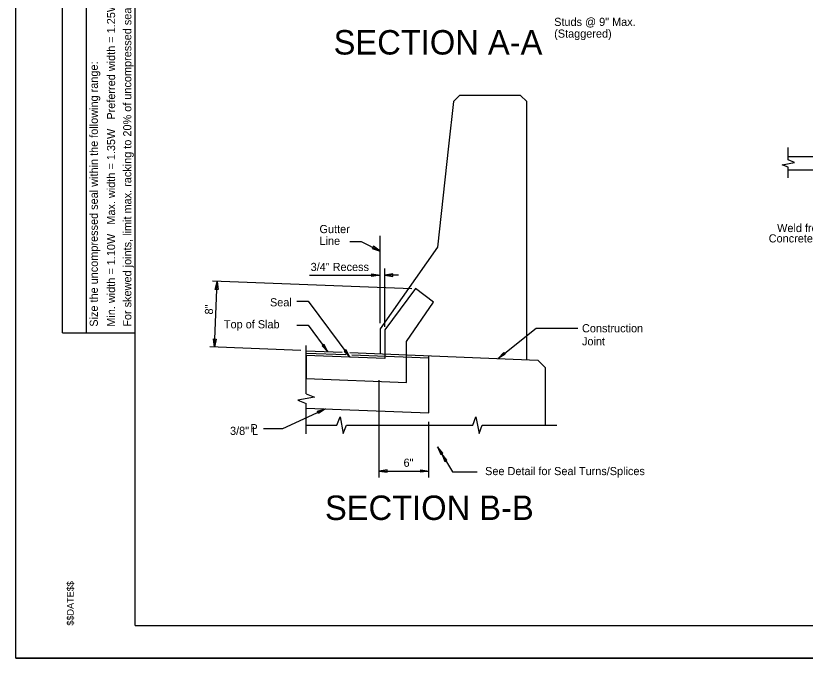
# Model space of a CAD drawing. Extents: x 3.7 to 39.9, y -2.3 to 19.7.
# Drawn here: x 3.74 to 15.85, y -2.32 to 7.54 of the extents above; entities that cross this region are included whole.
import ezdxf

# ---------------------------------------------------------------- set-up
doc = ezdxf.new("R2010")
doc.units = 0
for name, color, linetype in [('BR_AUTO DIMENSION', 7, 'Continuous'), ('BR_BORDER LINES', 7, 'Continuous'), ('BR_CENTER LINES', 7, 'Continuous'), ('BR_CONCRETE', 7, 'Continuous'), ('BR_REBAR', 7, 'Continuous'), ('BR_STRUCTURAL STEEL', 7, 'Continuous'), ('BR_TABLE LINES', 7, 'Continuous'), ('BR_TEXT', 7, 'Continuous'), ('RD_SHT_IplotShp', 7, 'Continuous')]:
    doc.layers.add(name, color=color, linetype=linetype)

msp = doc.modelspace()

# ---------------------------------------------------------------- linework, layer by layer
at = {"layer": 'BR_AUTO DIMENSION'}
for p, q in [((9.328, 2.823), (9.328, 4.162)), ((8.865, 4.077), (9.04, 4.077)), ((9.04, 4.077), (9.328, 3.929)), ((9.401, 2.766), (9.401, 3.66)), ((8.243, 3.56), (9.328, 3.56)), ((9.611, 3.56), (9.401, 3.56)), ((9.814, 3.351), (6.755, 3.467)), ((6.786, 2.455), (6.825, 3.464)), ((8.051, 3.163), (8.225, 3.163)), ((8.225, 3.163), (8.865, 2.302)), ((8.05, 2.795), (8.224, 2.795)), ((8.224, 2.795), (8.528, 2.386)), ((11.141, 2.283), (11.723, 2.749)), ((11.723, 2.749), (12.361, 2.749)), ((8.111, 2.405), (6.717, 2.458)), ((9.314, 0.454), (9.314, 1.947)), ((7.835, 1.205), (8.488, 1.508)), ((10.076, 0.454), (10.076, 1.312)), ((7.54, 1.205), (7.835, 1.205)), ((10.21, 0.926), (10.44, 0.544)), ((9.314, 0.555), (10.076, 0.555)), ((10.44, 0.544), (10.819, 0.544))]:
    msp.add_line(p, q, dxfattribs=at)
for points in [[(9.208, 3.97), (9.328, 3.929), (9.225, 4.003)], [(9.203, 3.579), (9.328, 3.56), (9.203, 3.541)], [(9.526, 3.579), (9.401, 3.56), (9.526, 3.541)], [(6.799, 3.34), (6.825, 3.464), (6.841, 3.339)], [(6.812, 2.579), (6.786, 2.455), (6.77, 2.581)], [(8.438, 2.476), (8.528, 2.386), (8.468, 2.498)], [(8.776, 2.391), (8.865, 2.302), (8.806, 2.413)], [(11.25, 2.346), (11.141, 2.283), (11.227, 2.375)], [(8.367, 1.473), (8.488, 1.508), (8.383, 1.439)], [(10.291, 0.829), (10.21, 0.926), (10.258, 0.809)], [(10.355, 0.722), (10.275, 0.819), (10.323, 0.702)], [(9.439, 0.574), (9.314, 0.555), (9.439, 0.536)], [(9.951, 0.574), (10.076, 0.555), (9.951, 0.536)]]:
    msp.add_lwpolyline(points, close=True, dxfattribs=at)
at = {"layer": 'BR_BORDER LINES'}
for p, q in [((5.57, -1.817), (5.57, 19.183)), ((5.57, -1.817), (39.236, -1.817)), ((3.736, -2.316), (39.736, -2.316))]:
    msp.add_line(p, q, dxfattribs=at)
at = {"layer": 'BR_CENTER LINES'}
for points in [[(8.192, 1.737), (8.321, 1.689), (8.064, 1.641), (8.192, 1.592)], [(8.666, 1.259), (8.715, 1.388), (8.763, 1.131), (8.811, 1.259)], [(10.752, 1.259), (10.8, 1.388), (10.848, 1.131), (10.896, 1.259)]]:
    msp.add_lwpolyline(points, dxfattribs=at)
at = {"layer": 'BR_CONCRETE'}
for p, q in [((10.547, 6.316), (10.453, 6.222)), ((11.484, 6.316), (10.547, 6.316)), ((11.578, 6.222), (11.484, 6.316)), ((10.453, 6.222), (10.378, 5.537)), ((11.578, 2.269), (11.578, 6.222)), ((10.378, 5.537), (10.209, 3.992)), ((10.209, 3.992), (9.328, 2.734)), ((9.328, 2.734), (9.328, 2.359)), ((8.192, 2.401), (8.748, 2.378)), ((8.863, 2.374), (11.748, 2.258)), ((9.457, 2.353), (9.457, 2.35)), ((10.076, 1.448), (10.076, 2.325)), ((11.866, 2.14), (11.748, 2.258)), ((11.866, 1.259), (11.866, 2.14))]:
    msp.add_line(p, q, dxfattribs=at)
at = {"layer": 'BR_REBAR'}
msp.add_line((8.192, 2.364), (8.804, 2.341), dxfattribs=at)
at = {"layer": 'BR_STRUCTURAL STEEL'}
for p, q in [((15.594, 5.383), (20.419, 5.383)), ((15.594, 5.177), (18.113, 5.177)), ((8.892, 2.338), (10.076, 2.293)), ((8.192, 1.519), (10.076, 1.448))]:
    msp.add_line(p, q, dxfattribs=at)
at = {"layer": 'BR_TABLE LINES'}
for p, q in [((4.455, 2.677), (4.455, 19.003)), ((4.82, 2.677), (4.82, 13.996)), ((15.594, 5.328), (15.594, 5.521)), ((15.594, 5.052), (15.594, 5.219)), ((4.455, 2.677), (5.57, 2.677)), ((8.192, 1.737), (8.192, 2.482)), ((8.192, 1.128), (8.192, 1.592)), ((8.192, 1.259), (8.666, 1.259)), ((8.811, 1.259), (10.752, 1.259)), ((10.896, 1.259), (12.042, 1.259))]:
    msp.add_line(p, q, dxfattribs=at)
msp.add_lwpolyline([(15.594, 5.219), (15.497, 5.255), (15.69, 5.291), (15.594, 5.328)], dxfattribs=at)
msp.add_lwpolyline([(8.192, 2.327), (8.192, 1.975), (9.733, 1.914), (9.733, 2.543), (10.147, 3.148), (9.871, 3.355), (9.401, 2.72), (9.401, 2.279)], close=True, dxfattribs=at)
at = {"layer": 'RD_SHT_IplotShp'}
msp.add_lwpolyline([(3.736, 19.683), (39.736, 19.683), (39.736, -2.317), (3.736, -2.317)], close=True, dxfattribs=at)

# ---------------------------------------------------------------- texts
at = {"layer": 'BR_TEXT'}
for s, height, rotation, p in [('For skewed joints, limit max. racking to 20% of uncompressed seal width.', 0.125, 90, (5.51, 2.769)), ('Min. width = 1.10W   Max. width = 1.35W   Preferred width = 1.25W.', 0.125, 90, (5.261, 2.769)), ('Size the uncompressed seal within the following range: ', 0.125, 90, (4.996, 2.769)), ('8"', 0.125, 87.8369, (6.762, 2.954)), ('$$DATE$$', 0.1042, 90, (4.625, -1.817))]:
    msp.add_text(s, height=height, rotation=rotation, dxfattribs=at).set_placement(p)
for s, height, p in [('Studs @ 9" Max.', 0.125, (12, 7.384)), ('SECTION A-A', 0.375, (8.615, 6.945)), ('(Staggered)', 0.125, (12, 7.204)), ('Gutter', 0.125, (8.398, 4.205)), ('Weld from', 0.125, (15.422, 4.221)), ('Line', 0.125, (8.398, 4.024)), ('Concrete Side', 0.125, (15.293, 4.062)), ('3/4" Recess', 0.125, (8.262, 3.624)), ('Seal', 0.125, (7.638, 3.081)), ('Top of Slab', 0.125, (6.931, 2.744)), ('Construction', 0.125, (12.427, 2.683)), ('Joint', 0.125, (12.427, 2.483)), ('3/8" L', 0.125, (7.025, 1.109)), ('P', 0.125, (7.338, 1.15)), ('6"', 0.125, (9.688, 0.62)), ('See Detail for Seal Turns/Splices', 0.125, (10.94, 0.492)), ('SECTION B-B', 0.375, (8.482, -0.196))]:
    msp.add_text(s, height=height, dxfattribs=at).set_placement(p)

doc.saveas('drawing.dxf')
